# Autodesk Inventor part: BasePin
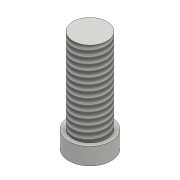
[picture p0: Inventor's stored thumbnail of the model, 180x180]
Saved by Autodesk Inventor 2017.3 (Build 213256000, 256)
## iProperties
Part Number: BasePin
Material: 一般
Document SubType Name: Modeling
Designer: kyushu-hep
Density: 1 g/cm^3
Appearance: 既定
Author: kyushu-hep
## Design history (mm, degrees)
sketch "スケッチ1"
  geometry: C1 r 2.5 at (0, 0); 1 further point
  constraints: 1 centre point, 1 coincident
  dimensions: "d0" = 5 diameter of C1
extrude "押し出し1" new body sketch "スケッチ1" distance "d1" = 2; taper "d2" = 0 deg
sketch "スケッチ2"
  geometry: C1 r 2 at (0, 0); 1 further point
  constraints: 1 centre point, 1 coincident
  dimensions: "d3" = 4 diameter of C1
extrude "押し出し2" join sketch "スケッチ2" distance "d4" = 10; taper "d5" = 0 deg
feature "ねじ1" dims "d6" = 10, "d7" = 0
node "ソリッド1"
